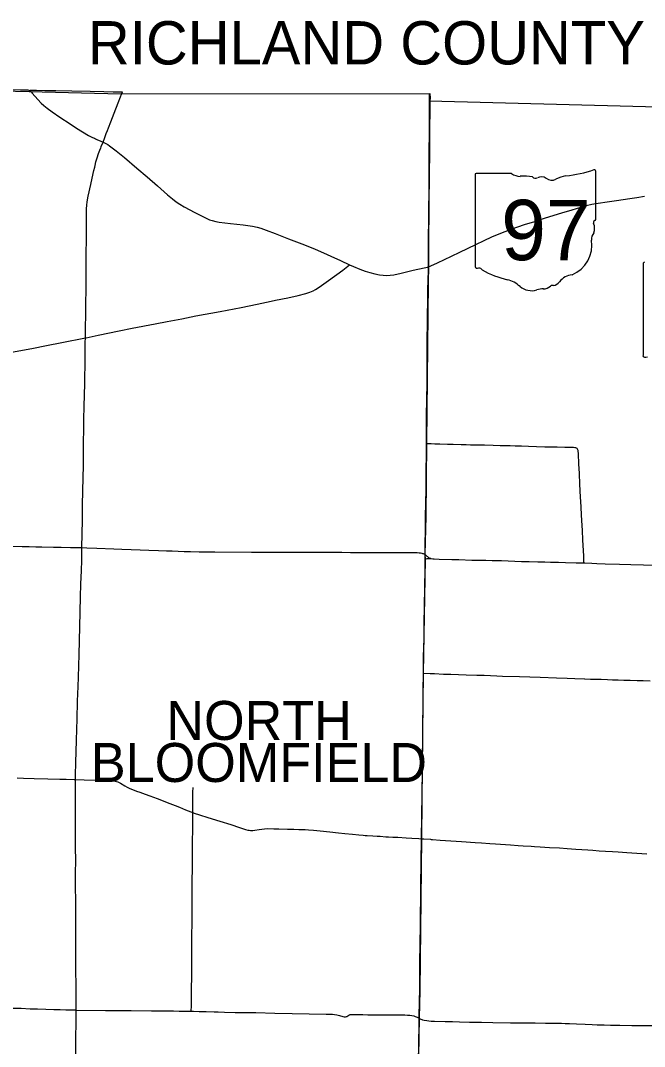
# Model space of a CAD drawing. Extents: x 9078 to 9739, y 4248 to 4966.
# Drawn here: x 9533 to 9605, y 4827.9 to 4946.2 of the extents above; entities that cross this region are included whole.
import ezdxf

# ---------------------------------------------------------------- set-up
doc = ezdxf.new("R2010")
doc.units = 0
for name, color, linetype in [('GM_X_Adjacent_County_Text', 7, 'Continuous'), ('GM_X_County', 7, 'Continuous'), ('GM_X_County_Road', 7, 'Continuous'), ('GM_X_State_Route', 7, 'Continuous'), ('GM_X_State_Shield', 7, 'Continuous'), ('GM_X_Township', 7, 'Continuous'), ('GM_X_Township_Road', 7, 'Continuous'), ('GM_X_Township_Text', 7, 'Continuous')]:
    doc.layers.add(name, color=color, linetype=linetype)

msp = doc.modelspace()

# ---------------------------------------------------------------- linework, layer by layer
at = {"layer": 'GM_X_County'}
msp.add_lwpolyline([(9527.58, 4938.18), (9534.01, 4938.03), (9544.57, 4937.79), (9580.15, 4937.8), (9580.15, 4936.95), (9612.46, 4936.11), (9625.64, 4935.77), (9665.53, 4934.74), (9665.86, 4916.26), (9666.54, 4891.17), (9666.82, 4882.14), (9667.42, 4855.9), (9649.93, 4856.23), (9641.33, 4856.41), (9641.51, 4850.43), (9641.44, 4845.14), (9641.45, 4844.73), (9641.78, 4828.99), (9642.12, 4813.07)], dxfattribs=at)
at = {"layer": 'GM_X_County_Road'}
for points in [[(9580.29, 4936.95), (9580.3, 4937.28), (9580.29, 4937.81)], [(9580.08, 4917.82), (9580.08, 4918.83), (9580.09, 4920.88), (9580.1, 4921.95), (9580.11, 4922.44), (9580.11, 4923.18), (9580.11, 4923.67), (9580.12, 4924.24), (9580.12, 4924.98), (9580.15, 4925.95), (9580.2, 4927.52), (9580.22, 4929.17), (9580.24, 4930.3), (9580.24, 4931.87), (9580.24, 4932.6), (9580.26, 4934.49), (9580.27, 4935.14), (9580.28, 4935.8), (9580.29, 4936.78), (9580.29, 4936.95)], [(9542.26, 4931.48), (9542.33, 4931.68), (9542.53, 4932.2)], [(9541.62, 4929.52), (9541.71, 4929.93), (9541.85, 4930.4), (9542, 4930.89), (9542.24, 4931.45), (9542.26, 4931.48)], [(9541.47, 4928.91), (9541.57, 4929.33), (9541.62, 4929.52)], [(9540.5, 4909.62), (9540.52, 4910.82), (9540.54, 4912.29), (9540.56, 4913.85), (9540.57, 4914.92), (9540.58, 4915.66), (9540.57, 4915.98), (9540.57, 4916.47), (9540.59, 4919.1), (9540.61, 4921.23), (9540.62, 4924.51), (9540.65, 4924.92), (9540.7, 4925.32), (9540.83, 4925.96), (9541.13, 4927.32), (9541.4, 4928.6), (9541.47, 4928.91)], [(9579.85, 4897.42), (9579.85, 4897.44), (9579.86, 4900.23), (9579.87, 4901.04), (9579.89, 4902.11), (9579.89, 4902.77), (9579.9, 4903.26), (9579.92, 4903.67), (9579.93, 4904.16), (9579.93, 4904.49), (9579.93, 4904.81), (9579.92, 4905.39), (9579.93, 4906.04), (9579.94, 4906.7), (9579.94, 4908.42), (9579.95, 4909.32), (9579.97, 4911.37), (9579.99, 4912.27), (9580.01, 4913.83), (9580.03, 4915.31), (9580.05, 4916.13), (9580.08, 4917.6), (9580.08, 4917.82)], [(9540.09, 4885.42), (9540.15, 4888.59), (9540.18, 4890.31), (9540.22, 4891.95), (9540.26, 4894.91), (9540.28, 4896.22), (9540.29, 4897.61), (9540.31, 4899.01), (9540.33, 4900.24), (9540.36, 4901.71), (9540.42, 4904.34), (9540.46, 4907.21), (9540.49, 4909.1), (9540.5, 4909.62)], [(9579.69, 4884.62), (9579.69, 4884.74), (9579.72, 4886.22), (9579.73, 4886.95), (9579.75, 4888.18), (9579.76, 4889.09), (9579.76, 4889.5), (9579.77, 4889.99), (9579.77, 4890.72), (9579.8, 4891.95), (9579.8, 4892.36), (9579.8, 4892.85), (9579.81, 4893.43), (9579.81, 4893.84), (9579.82, 4894.57), (9579.84, 4895.88), (9579.85, 4896.78), (9579.85, 4897.42)], [(9530.82, 4885.63), (9531.8, 4885.6), (9533.2, 4885.56), (9534.02, 4885.53), (9534.76, 4885.52), (9535.49, 4885.5), (9536.81, 4885.47), (9537.71, 4885.45), (9538.77, 4885.43), (9539.92, 4885.42), (9540.09, 4885.42)], [(9539.36, 4858.64), (9539.36, 4859.15), (9539.4, 4860.63), (9539.46, 4863.17), (9539.5, 4864.48), (9539.54, 4865.63), (9539.6, 4867.68), (9539.65, 4869.4), (9539.69, 4870.47), (9539.76, 4873.09), (9539.85, 4876.29), (9539.94, 4879.73), (9539.98, 4881.21), (9540.03, 4882.77), (9540.07, 4883.92), (9540.09, 4885.42)], [(9540.09, 4885.42), (9540.68, 4885.38), (9541.82, 4885.34), (9543.79, 4885.27), (9544.69, 4885.23), (9545.76, 4885.19), (9546.82, 4885.15), (9547.8, 4885.12), (9548.95, 4885.08), (9549.85, 4885.04), (9550.51, 4885.03), (9551.9, 4884.98), (9552.64, 4884.95), (9553.62, 4884.93), (9555.42, 4884.92), (9559.68, 4884.9), (9564.26, 4884.88), (9566.85, 4884.88), (9567.96, 4884.87), (9569.35, 4884.87), (9570.09, 4884.87), (9571.07, 4884.86), (9571.64, 4884.85), (9572.79, 4884.85), (9573.77, 4884.84), (9574.92, 4884.84), (9575.49, 4884.84), (9576.23, 4884.84), (9576.55, 4884.84), (9577.05, 4884.85), (9578.28, 4884.85), (9578.77, 4884.84), (9579.01, 4884.83), (9579.18, 4884.8), (9579.33, 4884.77), (9579.41, 4884.75), (9579.49, 4884.72), (9579.69, 4884.62)], [(9579.69, 4884.62), (9579.91, 4884.41), (9579.96, 4884.37), (9580.09, 4884.27), (9580.17, 4884.24), (9580.24, 4884.2), (9580.32, 4884.18), (9580.35, 4884.17)], [(9579.69, 4884.09), (9579.69, 4884.25), (9579.69, 4884.62)], [(9579.51, 4870.91), (9579.51, 4871.1), (9579.53, 4872.77), (9579.55, 4873.92), (9579.57, 4874.9), (9579.59, 4876.79), (9579.62, 4878.51), (9579.65, 4880.97), (9579.69, 4882.77), (9579.69, 4883.76), (9579.69, 4884.09)], [(9579.69, 4884.09), (9579.8, 4884.12), (9579.92, 4884.15), (9580.07, 4884.16), (9580.18, 4884.17), (9580.35, 4884.17)], [(9580.35, 4884.17), (9580.4, 4884.16), (9580.57, 4884.13), (9580.73, 4884.12), (9581.31, 4884.09), (9582.78, 4884.06), (9583.6, 4884.04), (9585.08, 4883.98), (9585.99, 4883.96), (9586.71, 4883.95), (9587.45, 4883.94), (9588.52, 4883.91), (9590.81, 4883.83), (9591.72, 4883.82), (9592.7, 4883.79), (9593.52, 4883.76), (9594.17, 4883.74), (9595.07, 4883.73), (9595.9, 4883.7), (9597.11, 4883.66), (9597.99, 4883.64)], [(9597.99, 4883.64), (9598.12, 4883.64), (9598.92, 4883.61), (9599.5, 4883.58), (9600.48, 4883.55), (9602.12, 4883.51), (9603.43, 4883.47), (9604.91, 4883.42), (9606.05, 4883.39), (9608.1, 4883.33), (9609.01, 4883.31), (9610.64, 4883.29), (9611.3, 4883.28), (9613.67, 4883.22), (9614.16, 4883.21), (9614.73, 4883.2)], [(9579.51, 4870.91), (9580.27, 4870.89), (9580.77, 4870.87), (9581.83, 4870.83), (9582.65, 4870.81), (9584.45, 4870.74), (9585.68, 4870.71), (9586.5, 4870.68), (9587.24, 4870.65), (9587.97, 4870.62), (9588.63, 4870.6), (9590.59, 4870.53), (9592.97, 4870.46), (9594.85, 4870.39), (9596.08, 4870.35), (9596.98, 4870.32), (9598.1, 4870.28)], [(9598.1, 4870.28), (9598.13, 4870.28), (9598.78, 4870.25), (9599.27, 4870.24), (9600.01, 4870.22), (9600.75, 4870.19), (9601.32, 4870.17), (9601.65, 4870.17), (9601.97, 4870.16), (9602.63, 4870.13), (9603.37, 4870.12), (9604.18, 4870.1), (9604.84, 4870.07), (9605.66, 4870.04)], [(9539.44, 4832.06), (9539.44, 4832.75), (9539.44, 4833.74), (9539.43, 4835.05), (9539.41, 4836.52), (9539.41, 4837.75), (9539.4, 4838.65), (9539.41, 4839.56), (9539.4, 4841.2), (9539.4, 4842.1), (9539.39, 4843.82), (9539.38, 4844.89), (9539.37, 4846.03), (9539.37, 4847.43), (9539.37, 4848.08), (9539.38, 4849.07), (9539.37, 4851.03), (9539.36, 4852.92), (9539.36, 4853.9), (9539.35, 4854.64), (9539.35, 4855.46), (9539.35, 4856.12), (9539.35, 4856.94), (9539.35, 4857.84), (9539.36, 4858.33), (9539.36, 4858.64)], [(9532.18, 4832.29), (9533.08, 4832.26), (9534.14, 4832.21), (9534.96, 4832.19), (9535.95, 4832.16), (9536.85, 4832.12), (9537.59, 4832.11), (9538.24, 4832.09), (9539.31, 4832.07), (9539.44, 4832.06)], [(9539.39, 4826.93), (9539.4, 4828.16), (9539.41, 4829.07), (9539.43, 4830.38), (9539.44, 4830.87), (9539.44, 4831.52), (9539.44, 4831.85), (9539.44, 4832.06)], [(9539.44, 4832.06), (9542.81, 4832.02), (9544.04, 4832), (9545.76, 4831.99), (9548.14, 4831.96), (9549.12, 4831.95), (9550.02, 4831.95), (9550.67, 4831.95), (9551.32, 4831.93), (9552.14, 4831.91), (9552.72, 4831.91)], [(9552.72, 4831.91), (9552.96, 4831.91), (9553.62, 4831.89), (9554.03, 4831.88), (9554.44, 4831.87), (9555.34, 4831.85), (9555.83, 4831.84), (9556.56, 4831.82), (9557.79, 4831.79), (9558.37, 4831.78), (9558.94, 4831.78), (9560.17, 4831.76), (9562.37, 4831.7), (9564.35, 4831.65), (9568.27, 4831.6), (9568.76, 4831.59), (9569.01, 4831.58), (9569.25, 4831.55), (9569.5, 4831.51), (9569.81, 4831.43), (9570.21, 4831.31), (9570.37, 4831.28), (9570.45, 4831.28), (9570.53, 4831.28), (9570.61, 4831.3), (9570.68, 4831.33), (9570.89, 4831.47), (9570.96, 4831.51), (9571.04, 4831.53), (9571.12, 4831.55), (9571.2, 4831.56), (9571.44, 4831.56), (9571.94, 4831.54), (9572.51, 4831.53), (9573.08, 4831.51), (9573.66, 4831.51), (9574.15, 4831.51), (9575.05, 4831.49), (9575.87, 4831.49), (9576.61, 4831.5), (9577.34, 4831.49), (9577.67, 4831.48), (9577.92, 4831.46), (9578.16, 4831.42), (9578.4, 4831.37), (9578.56, 4831.33), (9578.79, 4831.24), (9578.85, 4831.21), (9578.94, 4831.16), (9579.03, 4831.11)], [(9579.03, 4831.11), (9579.11, 4831.06), (9579.19, 4831.02), (9579.3, 4830.97), (9579.4, 4830.94), (9579.57, 4830.89), (9579.89, 4830.84), (9580.13, 4830.8), (9580.38, 4830.78), (9580.79, 4830.77), (9582.02, 4830.74), (9582.84, 4830.72), (9583.66, 4830.7), (9584.81, 4830.67), (9585.63, 4830.66), (9585.99, 4830.65)], [(9585.99, 4830.65), (9586.2, 4830.64), (9587.52, 4830.63), (9589.55, 4830.6), (9590.37, 4830.59), (9591.38, 4830.58), (9592.39, 4830.57), (9593.57, 4830.55), (9594.22, 4830.54), (9594.47, 4830.54), (9594.72, 4830.54), (9595.45, 4830.53), (9595.86, 4830.51), (9596.35, 4830.49), (9597.17, 4830.46), (9598.16, 4830.41), (9598.97, 4830.38), (9599.55, 4830.36), (9600.37, 4830.34), (9601.1, 4830.32), (9602.17, 4830.3), (9603.54, 4830.29), (9606.03, 4830.26)]]:
    msp.add_lwpolyline(points, dxfattribs=at)
at = {"layer": 'GM_X_State_Route'}
for points in [[(9527.71, 4938.29), (9527.74, 4938.29), (9528.41, 4938.28), (9531.44, 4938.26), (9533, 4938.25), (9533.56, 4938.24), (9533.8, 4938.23), (9533.86, 4938.23), (9533.97, 4938.2), (9534.05, 4938.16), (9534.1, 4938.13)], [(9534.1, 4938.13), (9534.15, 4938.1), (9534.21, 4938.05), (9534.29, 4937.96), (9534.36, 4937.87), (9535, 4937.12), (9535.39, 4936.69), (9535.69, 4936.41), (9536.08, 4936.11), (9536.68, 4935.68), (9537.56, 4935.07), (9538.73, 4934.32), (9539.49, 4933.83), (9540.17, 4933.39), (9540.87, 4932.96), (9541.33, 4932.74), (9541.44, 4932.69), (9541.53, 4932.65), (9541.68, 4932.59), (9541.83, 4932.52), (9542.27, 4932.33), (9542.53, 4932.2), (9542.71, 4932.12), (9543.07, 4931.92), (9543.27, 4931.78), (9543.6, 4931.55), (9544.06, 4931.2), (9545, 4930.42), (9546.45, 4929.2), (9547.63, 4928.19), (9548.8, 4927.16), (9549.97, 4926.12), (9550.53, 4925.65), (9550.99, 4925.3), (9551.4, 4925.03), (9551.9, 4924.74), (9553.14, 4924.1), (9554.45, 4923.42), (9554.83, 4923.25), (9555.14, 4923.14), (9555.54, 4923.04), (9555.94, 4922.97), (9557.25, 4922.82), (9558.72, 4922.64), (9559.77, 4922.5), (9560.33, 4922.39), (9560.73, 4922.28), (9561.34, 4922.05), (9562.41, 4921.64), (9563.95, 4921.06), (9565.79, 4920.36), (9567, 4919.87), (9567.98, 4919.43), (9568.8, 4919.06), (9569.92, 4918.54), (9570.96, 4918.04), (9571.42, 4917.87), (9572.17, 4917.54), (9572.78, 4917.31), (9573.33, 4917.14), (9573.88, 4917.01), (9574.45, 4916.9), (9574.85, 4916.85), (9575.26, 4916.82), (9575.67, 4916.84), (9576.07, 4916.89), (9576.95, 4917.09), (9578.3, 4917.41), (9579.59, 4917.69), (9579.98, 4917.79), (9580.08, 4917.82), (9580.37, 4917.93), (9581.11, 4918.27), (9582.74, 4919.04), (9583.71, 4919.49), (9585.55, 4920.39), (9586.52, 4920.84), (9587.41, 4921.26), (9588.24, 4921.61), (9589.61, 4922.15), (9590.39, 4922.43), (9591.17, 4922.68), (9592.34, 4923.05), (9593.59, 4923.47), (9595.47, 4924.04), (9596.65, 4924.4), (9597.67, 4924.69), (9598.3, 4924.88), (9598.94, 4925.04), (9599.66, 4925.17), (9600.72, 4925.32), (9601.78, 4925.47), (9603.32, 4925.69), (9604.13, 4925.81), (9605.02, 4925.96)], [(9531.99, 4907.95), (9534.32, 4908.4), (9536.01, 4908.73), (9537.78, 4909.08), (9540.5, 4909.62), (9540.6, 4909.63), (9541.96, 4909.92), (9544.38, 4910.42), (9545.9, 4910.72), (9548.56, 4911.24), (9549.93, 4911.51), (9551.62, 4911.83), (9553.24, 4912.14), (9556.06, 4912.67), (9558.48, 4913.13), (9560.33, 4913.49), (9561.93, 4913.84), (9562.44, 4913.95), (9563.86, 4914.25), (9565.06, 4914.52), (9565.93, 4914.74), (9566.4, 4914.89), (9566.77, 4915.04), (9567.06, 4915.19), (9567.48, 4915.46), (9568.54, 4916.22), (9570.2, 4917.43), (9570.78, 4917.89), (9570.96, 4918.04)]]:
    msp.add_lwpolyline(points, dxfattribs=at)
at = {"layer": 'GM_X_State_Shield'}
for p, q in [((9585.46, 4928.41), (9585.46, 4917.84)), ((9589.68, 4928.59), (9585.6, 4928.59)), ((9599.39, 4923.32), (9599.39, 4928.85)), ((9599.39, 4923.32), (9599.39, 4923.32)), ((9604.84, 4918.15), (9604.84, 4907.59))]:
    msp.add_line(p, q, dxfattribs=at)
for centre, radius, start, end in [((9585.62, 4928.43), 0.161, 98.1301, 188.1301), ((9590.65, 4929.81), 1.56, 231.6195, 271.1119), ((9591.17, 4922.66), 5.62, 80.4867, 94.9883), ((9592.44, 4928.48), 0.451, 219.7921, 297.1024), ((9593.11, 4927.26), 0.938, 54.4667, 119.1411), ((9596.31, 4925.36), 2.97, 97.3462, 120.7689), ((9594.43, 4942.99), 14.76, 275.8445, 288.9065), ((9599.23, 4928.87), 0.155, 351.8621, 97.738), ((9594.32, 4928.94), 1.13, 233.8562, 294.8282), ((9599.35, 4922.92), 0.24, 107.944, 210.337), ((9597.82, 4922.22), 1.44, 340.033, 23.6496), ((9599.22, 4923.3), 0.166, 289.6038, 7.7341), ((9599.94, 4921.01), 1.05, 136.8065, 186.9296), ((9595.25, 4920.31), 3.69, 292.3089, 8.9858), ((9585.63, 4917.82), 0.163, 171.9584, 258.3066), ((9585.65, 4918.9), 1.24, 267.339, 280.6039), ((9585.9, 4917.23), 0.448, 29.7484, 93.2717), ((9591.56, 4926.72), 10.66, 240.4129, 257.1985), ((9596.81, 4914.87), 2.02, 94.4031, 142.5768), ((9588.38, 4913.09), 3.34, 47.1842, 75.836), ((9591.99, 4917.18), 2.12, 230.7004, 286.2918), ((9593.21, 4913.52), 1.74, 85.6951, 111.2099), ((9593.36, 4916.39), 1.13, 268.777, 315.5493), ((9594.38, 4915.36), 0.318, 65.7517, 132.6484), ((9594.25, 4916.81), 1.19, 282.8732, 323.2771)]:
    msp.add_arc(centre, radius, start, end, dxfattribs=at)
for centre, major_axis, start_param, end_param in [((9605.04, 4918.18), (0.202, 0), 1.712693, 3.28349), ((9605.04, 4907.56), (0.203, 0), 3.00124, 4.508301), ((9605.07, 4908.64), (1.55, 0), 4.665946, 4.897461)]:
    msp.add_ellipse(centre, major_axis=major_axis, ratio=0.8, start_param=start_param, end_param=end_param, dxfattribs=at)
at = {"layer": 'GM_X_Township'}
msp.add_lwpolyline([(9580.15, 4937.8), (9580.15, 4936.95), (9580.08, 4917.87), (9580.06, 4916.03), (9579.84, 4897.51), (9579.77, 4888.99), (9579.65, 4884.67), (9579.69, 4884.1), (9579.47, 4870.94), (9579.37, 4860.56), (9579.29, 4851.87), (9579.08, 4834.3), (9579.03, 4831.16), (9578.94, 4826.71), (9578.72, 4804.83)], dxfattribs=at)
at = {"layer": 'GM_X_Township_Road'}
for points in [[(9534.1, 4938.13), (9534.16, 4938.18), (9534.2, 4938.2), (9534.25, 4938.21), (9534.35, 4938.21), (9534.84, 4938.2), (9535.83, 4938.17), (9536.49, 4938.15), (9537.07, 4938.14), (9538.95, 4938.11), (9541.06, 4938.08), (9542.61, 4938.05), (9543.69, 4938.02), (9544.77, 4938.01)], [(9542.53, 4932.2), (9542.73, 4932.72), (9542.91, 4933.18), (9543.04, 4933.55), (9543.16, 4933.86), (9543.42, 4934.54), (9543.81, 4935.53), (9544.28, 4936.75), (9544.55, 4937.44), (9544.67, 4937.73), (9544.77, 4938.01)], [(9579.85, 4897.42), (9580, 4897.42), (9580.41, 4897.41), (9580.82, 4897.4), (9581.39, 4897.39), (9582.29, 4897.36), (9582.95, 4897.34), (9583.85, 4897.32), (9584.43, 4897.3), (9584.92, 4897.29), (9586.23, 4897.27), (9586.56, 4897.26), (9587.54, 4897.23), (9588.36, 4897.2), (9589.5, 4897.18), (9590.09, 4897.16), (9590.82, 4897.14), (9591.64, 4897.11), (9592.55, 4897.09), (9593.53, 4897.06), (9594.27, 4897.04), (9594.93, 4897.03), (9595.83, 4897.01), (9596.16, 4897.01), (9596.4, 4897), (9596.81, 4896.99), (9596.98, 4896.97), (9597.06, 4896.95), (9597.13, 4896.91), (9597.2, 4896.87), (9597.26, 4896.81), (9597.3, 4896.74), (9597.32, 4896.66), (9597.33, 4896.58), (9597.35, 4896.25), (9597.4, 4895.1), (9597.46, 4893.95), (9597.52, 4892.72), (9597.6, 4891.25), (9597.62, 4890.75), (9597.67, 4890.1), (9597.71, 4889.2), (9597.74, 4888.54), (9597.82, 4887.39), (9597.87, 4886.33), (9597.96, 4884.44), (9597.99, 4883.64)], [(9579.38, 4858.3), (9579.38, 4858.44), (9579.39, 4859.34), (9579.41, 4860.24), (9579.41, 4860.73), (9579.41, 4861.55), (9579.42, 4862.21), (9579.43, 4863.11), (9579.45, 4864.75), (9579.46, 4867.46), (9579.48, 4868.77), (9579.49, 4869.67), (9579.5, 4870.16), (9579.5, 4870.57), (9579.51, 4870.91)], [(9532.63, 4858.85), (9533.37, 4858.82), (9534.6, 4858.79), (9536.16, 4858.75), (9537.55, 4858.7), (9538.29, 4858.68), (9539.19, 4858.65), (9539.36, 4858.64)], [(9539.36, 4858.64), (9540.34, 4858.62), (9542.06, 4858.59), (9543.05, 4858.57), (9543.37, 4858.56), (9543.62, 4858.54), (9543.78, 4858.51), (9543.94, 4858.47), (9544.1, 4858.42), (9544.25, 4858.37), (9544.4, 4858.3), (9544.54, 4858.22), (9545.03, 4857.92), (9545.32, 4857.77), (9545.62, 4857.63), (9545.92, 4857.5), (9546.38, 4857.32), (9546.77, 4857.18), (9547.38, 4856.96), (9547.93, 4856.77), (9548.77, 4856.45), (9550.23, 4855.9), (9550.84, 4855.66), (9551.37, 4855.45), (9552.05, 4855.16), (9552.66, 4854.92), (9552.9, 4854.84)], [(9552.9, 4854.84), (9552.9, 4854.88), (9552.9, 4855.09), (9552.9, 4855.41), (9552.9, 4855.66), (9552.9, 4856.03), (9552.91, 4856.77), (9552.91, 4857.18), (9552.92, 4857.75)], [(9579.29, 4851.83), (9579.28, 4852.21), (9579.29, 4852.62), (9579.31, 4853.6), (9579.31, 4854.1), (9579.32, 4854.59), (9579.33, 4855), (9579.33, 4855.41), (9579.34, 4855.98), (9579.34, 4856.31), (9579.35, 4856.72), (9579.37, 4857.95), (9579.38, 4858.3)], [(9552.72, 4831.91), (9552.72, 4832.02), (9552.73, 4832.45), (9552.75, 4833.36), (9552.76, 4834.05), (9552.76, 4834.55), (9552.77, 4835.88), (9552.77, 4837.77), (9552.78, 4838.51), (9552.78, 4839.74), (9552.78, 4840.65), (9552.8, 4842.13), (9552.8, 4843.03), (9552.81, 4843.7), (9552.81, 4844.07), (9552.81, 4844.55), (9552.82, 4844.97), (9552.82, 4845.31), (9552.82, 4845.61), (9552.82, 4845.93), (9552.82, 4846.28), (9552.83, 4847.27), (9552.83, 4847.59), (9552.84, 4847.76), (9552.85, 4848.17), (9552.86, 4848.48), (9552.86, 4848.74), (9552.86, 4848.99), (9552.86, 4849.81), (9552.85, 4850.22), (9552.86, 4850.96), (9552.88, 4853.42), (9552.89, 4854.08), (9552.89, 4854.63), (9552.9, 4854.84)], [(9552.9, 4854.84), (9553.05, 4854.78), (9553.67, 4854.59), (9554.61, 4854.29), (9556.02, 4853.84), (9557.27, 4853.45), (9558.29, 4853.12), (9558.99, 4852.89), (9559.23, 4852.83), (9559.39, 4852.8), (9559.55, 4852.79), (9559.8, 4852.79), (9560.04, 4852.82), (9560.53, 4852.9), (9560.85, 4852.94), (9561.18, 4852.97), (9561.51, 4852.99), (9562.25, 4852.98), (9562.82, 4852.97), (9563.8, 4852.94), (9564.54, 4852.91), (9565.11, 4852.9), (9565.85, 4852.87), (9566.26, 4852.84), (9566.83, 4852.8), (9567.57, 4852.73), (9568.71, 4852.62), (9569.69, 4852.52), (9570.42, 4852.44), (9571.32, 4852.35), (9572.06, 4852.28), (9572.55, 4852.24), (9572.78, 4852.21), (9573.03, 4852.2), (9573.68, 4852.15), (9574.17, 4852.13), (9574.5, 4852.11), (9575.15, 4852.06), (9575.48, 4852.04), (9575.97, 4852.01), (9576.54, 4851.99), (9577.52, 4851.94), (9578.18, 4851.9), (9578.99, 4851.85), (9579.29, 4851.83)], [(9579.03, 4831.11), (9579.03, 4831.15), (9579.03, 4831.81), (9579.04, 4832.54), (9579.06, 4833.45), (9579.07, 4834.1), (9579.08, 4834.68), (9579.09, 4835.66), (9579.09, 4836.64), (9579.09, 4837.13), (9579.1, 4838.28), (9579.11, 4838.93), (9579.13, 4840.24), (9579.15, 4841.31), (9579.16, 4842.13), (9579.16, 4842.62), (9579.18, 4843.6), (9579.19, 4844.42), (9579.2, 4845.24), (9579.21, 4846.06), (9579.22, 4847.29), (9579.24, 4848.28), (9579.25, 4849.18), (9579.26, 4850.25), (9579.27, 4850.74), (9579.28, 4851.39), (9579.29, 4851.8), (9579.29, 4851.83)], [(9579.29, 4851.83), (9579.56, 4851.81), (9580.3, 4851.76), (9580.38, 4851.75), (9580.55, 4851.73), (9581.45, 4851.67), (9583.9, 4851.5), (9585.46, 4851.39), (9586.19, 4851.34), (9587.18, 4851.29), (9587.83, 4851.25), (9589.55, 4851.13), (9590.45, 4851.06), (9591.02, 4851.02), (9591.92, 4850.96), (9592.33, 4850.94), (9592.99, 4850.89), (9594.05, 4850.82), (9595.2, 4850.76), (9596.1, 4850.69), (9597.08, 4850.62), (9598.47, 4850.53), (9599.04, 4850.49), (9599.78, 4850.44), (9600.52, 4850.39), (9601.33, 4850.34), (9601.99, 4850.3), (9602.97, 4850.24), (9604.12, 4850.16), (9605.27, 4850.09)], [(9578.95, 4826.54), (9578.95, 4826.56), (9578.97, 4827.71), (9578.98, 4828.04), (9578.98, 4828.36), (9578.99, 4828.77), (9579.01, 4829.84), (9579.03, 4830.66), (9579.03, 4831.11)]]:
    msp.add_lwpolyline(points, dxfattribs=at)

# ---------------------------------------------------------------- texts
at = {"layer": 'GM_X_Adjacent_County_Text'}
msp.add_text('RICHLAND COUNTY', height=5, dxfattribs=at).set_placement((9540.79, 4941.16))
at = {"layer": 'GM_X_State_Shield'}
msp.add_text('97', height=6.961, dxfattribs=at).set_placement((9588.47, 4918.58))
at = {"layer": 'GM_X_Township_Text'}
for s, p in [('NORTH', (9549.84, 4863.22)), ('BLOOMFIELD', (9541.13, 4858.37))]:
    msp.add_text(s, height=4.5, rotation=0, dxfattribs=at).set_placement(p)

doc.saveas('drawing.dxf')
